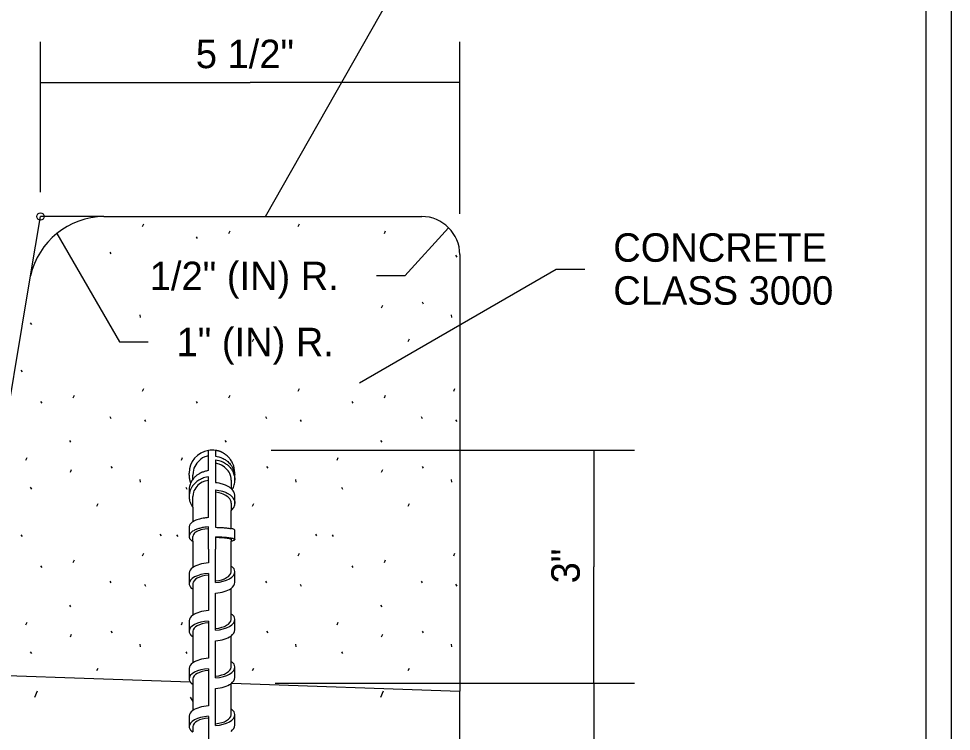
# Model space of a CAD drawing. Extents: x 99988 to 100172, y 99995 to 100047.
# Drawn here: x 100013.519 to 100015.812, y 100006.848 to 100008.601 of the extents above; entities that cross this region are included whole.
import ezdxf

# ---------------------------------------------------------------- set-up
doc = ezdxf.new("R2010")
doc.units = 0
for name, color, linetype in [('Level 1', 7, 'Continuous'), ('Level 10', 7, 'Continuous'), ('Level 15', 7, 'Continuous'), ('Level 2', 7, 'Continuous'), ('Level 20', 7, 'Continuous'), ('Level 3', 7, 'Continuous'), ('SH_GI_PlotLimits', 7, 'Continuous'), ('SH_GI_SheetBorder', 7, 'Continuous')]:
    doc.layers.add(name, color=color, linetype=linetype)

msp = doc.modelspace()

# ---------------------------------------------------------------- linework, layer by layer
at = {"layer": 'Level 1'}
for p, q in [((100013.7286, 100008.1139), (100014.51, 100008.1139)), ((100014.6037, 100008.0202), (100014.6037, 100006.9464)), ((100013.385, 100006.9889), (100013.5482, 100007.9682))]:
    msp.add_line(p, q, dxfattribs=at)
for centre, radius, start, end in [((100013.731, 100007.9264), 0.1875, 90.7439, 167.1228), ((100014.51, 100008.0202), 0.0937, 0, 90)]:
    msp.add_arc(centre, radius, start, end, dxfattribs=at)
at = {"layer": 'Level 10'}
for p, q in [((100013.9856, 100007.4889), (100013.9856, 100007.5387)), ((100014.0031, 100007.5387), (100014.0031, 100007.5247)), ((100014.0031, 100007.5157), (100014.0031, 100007.4599)), ((100013.9382, 100007.4781), (100013.9382, 100007.4828)), ((100013.9475, 100007.4678), (100013.9475, 100007.4781)), ((100013.9856, 100007.3733), (100013.9856, 100007.4736)), ((100014.0412, 100007.4656), (100014.0412, 100007.4451)), ((100014.0505, 100007.4656), (100014.0505, 100007.4742)), ((100013.9382, 100007.4413), (100013.9382, 100007.4251)), ((100014.0031, 100007.4418), (100014.0031, 100007.3495)), ((100013.9475, 100007.3987), (100013.9475, 100007.4251)), ((100014.0505, 100007.4086), (100014.0505, 100007.4265)), ((100013.9475, 100007.3987), (100013.9475, 100007.3631)), ((100014.0412, 100007.4086), (100014.0412, 100007.3902)), ((100014.0412, 100007.3464), (100014.0412, 100007.3902)), ((100013.9382, 100007.3503), (100013.9382, 100007.327)), ((100013.9856, 100007.2958), (100013.9856, 100007.3505)), ((100013.9475, 100007.3152), (100013.9475, 100007.327)), ((100014.0031, 100007.3264), (100014.0031, 100007.2958)), ((100014.0505, 100007.3196), (100014.0505, 100007.3426)), ((100013.9475, 100007.3152), (100013.9475, 100007.2958)), ((100014.0412, 100007.3196), (100014.0412, 100007.3158)), ((100014.0412, 100007.2958), (100014.0412, 100007.3158)), ((100013.9475, 100007.2958), (100013.9475, 100007.2508)), ((100014.0412, 100007.2538), (100014.0412, 100007.2958)), ((100014.0412, 100007.2402), (100014.0412, 100007.2538)), ((100013.9382, 100007.2368), (100013.9382, 100007.211)), ((100014.0505, 100007.2142), (100014.0505, 100007.2402)), ((100013.9475, 100007.211), (100013.9475, 100007.1979)), ((100013.9475, 100007.1979), (100013.9475, 100007.1336)), ((100014.0412, 100007.1366), (100014.0412, 100007.1992)), ((100013.9382, 100007.1196), (100013.9382, 100007.0939)), ((100014.0412, 100007.123), (100014.0412, 100007.1366)), ((100014.0412, 100007.1366), (100014.0412, 100007.1366)), ((100014.0505, 100007.097), (100014.0505, 100007.123)), ((100013.9475, 100007.0939), (100013.9475, 100007.0807)), ((100013.9475, 100007.0807), (100013.9475, 100007.0164)), ((100014.0412, 100007.0194), (100014.0412, 100007.0821)), ((100013.9382, 100007.0024), (100013.9382, 100006.9767)), ((100014.0412, 100007.0058), (100014.0412, 100007.0194)), ((100014.0505, 100006.9798), (100014.0505, 100007.0058)), ((100013.9475, 100006.9767), (100013.9475, 100006.9635)), ((100013.9475, 100006.9635), (100013.9475, 100006.8992)), ((100014.0412, 100006.9022), (100014.0412, 100006.9649)), ((100014.0412, 100006.8886), (100014.0412, 100006.9022)), ((100014.0505, 100006.8626), (100014.0505, 100006.8886)), ((100013.9382, 100006.8852), (100013.9382, 100006.8595)), ((100013.9475, 100006.8595), (100013.9475, 100006.8463))]:
    msp.add_line(p, q, dxfattribs=at)
for start, end in [(98.9444, 180.4882), (81.0556, 98.9444), (355.141, 17.7564)]:
    msp.add_arc((100013.9943, 100007.4833), 0.0561, start, end, dxfattribs=at)
for centre, major_axis, ratio, start_param, end_param in [((100013.9943, 100007.2368), (-0.0561, 0), 0.453331, 4.868499, 5.701022), ((100013.9943, 100007.211), (-0.0561, 0), 0.453331, 4.868499, 6.287318), ((100013.9943, 100007.2368), (-0.0561, 0), 0.453331, 5.701022, 6.28324), ((100013.9943, 100007.211), (-0.0469, 0), 0.453331, 4.899667, 6.283186), ((100013.9943, 100007.2402), (-0.0561, 0), 0.483341, 1.726906, 3.165641), ((100013.9943, 100007.2402), (0.0469, 0), 0.483341, 4.899667, 6.283186), ((100013.9943, 100007.2402), (-0.0561, 0), 0.483341, 3.165641, 3.398624), ((100013.9943, 100007.211), (-0.0561, 0), 0.453331, 0.005317, 0.291099), ((100013.9943, 100007.2142), (-0.0561, 0), 0.483341, 2.55865, 3.141593), ((100013.9943, 100007.2142), (-0.0561, 0), 0.483341, 1.726906, 2.55865), ((100013.9943, 100007.1196), (-0.0561, 0), 0.453331, 4.868499, 5.700703), ((100013.9943, 100007.0939), (-0.0561, 0), 0.453331, 4.868499, 6.289862), ((100013.9943, 100007.1196), (-0.0561, 0), 0.453331, 5.700723, 6.28324), ((100013.9943, 100007.123), (-0.0561, 0), 0.483341, 1.726906, 3.153527), ((100013.9943, 100007.123), (0.0469, 0), 0.483341, 4.899667, 6.283186), ((100013.9943, 100007.123), (-0.0561, 0), 0.483341, 3.153527, 3.398624), ((100013.9943, 100007.0939), (-0.0561, 0), 0.453331, 0.006676, 0.291099), ((100013.9943, 100007.0939), (-0.0469, 0), 0.453331, 4.899667, 6.283186), ((100013.9943, 100007.097), (-0.0561, 0), 0.483341, 2.558898, 3.141593), ((100013.9943, 100007.097), (-0.0561, 0), 0.483341, 1.726906, 2.558854), ((100013.9943, 100007.0024), (-0.0561, 0), 0.453331, 4.868499, 5.700722), ((100013.9943, 100006.9767), (-0.0561, 0), 0.453331, 4.868499, 6.28993), ((100013.9943, 100007.0024), (-0.0561, 0), 0.453331, 5.700722, 6.28324), ((100013.9943, 100007.0058), (-0.0561, 0), 0.483341, 1.726906, 3.170592), ((100013.9943, 100007.0058), (0.0469, 0), 0.483341, 4.899667, 6.283186), ((100013.9943, 100007.0058), (-0.0561, 0), 0.483341, 3.170592, 3.398624), ((100013.9943, 100006.9767), (-0.0469, 0), 0.453331, 4.899667, 6.283186), ((100013.9943, 100006.9798), (-0.0561, 0), 0.483341, 2.558843, 3.141593), ((100013.9943, 100006.9767), (-0.0561, 0), 0.453331, 0.006745, 0.291099), ((100013.9943, 100006.9798), (-0.0561, 0), 0.483341, 1.726906, 2.558843), ((100013.9943, 100006.8852), (-0.0561, 0), 0.453331, 4.868499, 5.701512), ((100013.9943, 100006.8852), (-0.0561, 0), 0.453331, 5.701512, 6.28324), ((100013.9943, 100006.8886), (-0.0561, 0), 0.483341, 1.726906, 3.160103), ((100013.9943, 100006.8886), (0.0469, 0), 0.483341, 4.899667, 6.283186), ((100013.9943, 100006.8886), (-0.0561, 0), 0.483341, 3.161599, 3.398624), ((100013.9943, 100006.8595), (-0.0561, 0), 0.453331, 4.868499, 6.300734), ((100013.9943, 100006.8595), (-0.0469, 0), 0.453331, 4.899667, 6.283186), ((100013.9943, 100006.8595), (-0.0561, 0), 0.453331, 0.017549, 0.291099), ((100013.9943, 100006.8626), (-0.0561, 0), 0.483341, 2.559264, 3.141593)]:
    msp.add_ellipse(centre, major_axis=major_axis, ratio=ratio, start_param=start_param, end_param=end_param, dxfattribs=at)
for points, degree in [([(100014.0236, 100007.5312), (100014.0173, 100007.535), (100014.0103, 100007.5376), (100014.0031, 100007.5387)], 2), ([(100014.0478, 100007.5004), (100014.0459, 100007.5064), (100014.0429, 100007.5122), (100014.0368, 100007.5202), (100014.0344, 100007.5227), (100014.0293, 100007.5273), (100014.0266, 100007.5294), (100014.0236, 100007.5312)], 3), ([(100013.9856, 100007.5254), (100013.9719, 100007.5217), (100013.9631, 100007.5155), (100013.9508, 100007.4989), (100013.9475, 100007.4885), (100013.9475, 100007.4781)], 3), ([(100014.0031, 100007.5247), (100014.0096, 100007.5237), (100014.016, 100007.5217), (100014.0276, 100007.5158), (100014.0328, 100007.5119), (100014.0414, 100007.5027), (100014.0448, 100007.4974), (100014.0488, 100007.4875), (100014.0499, 100007.4829), (100014.0503, 100007.4784)], 3), ([(100014.0031, 100007.5157), (100014.0164, 100007.5126), (100014.0222, 100007.51), (100014.0324, 100007.5034), (100014.0369, 100007.4992), (100014.044, 100007.4899), (100014.0468, 100007.4846), (100014.0498, 100007.4747), (100014.0505, 100007.4701), (100014.0505, 100007.4655)], 3), ([(100014.0412, 100007.4656), (100014.0412, 100007.4656), (100014.0412, 100007.4656), (100014.0412, 100007.4749), (100014.0377, 100007.4842), (100014.0254, 100007.4985), (100014.0169, 100007.5038), (100014.0031, 100007.5074)], 3), ([(100013.9856, 100007.4889), (100013.981, 100007.4883), (100013.9765, 100007.4871), (100013.9679, 100007.484), (100013.9639, 100007.482), (100013.9565, 100007.4771), (100013.9531, 100007.4743), (100013.9474, 100007.468), (100013.9449, 100007.4646), (100013.9426, 100007.46), (100013.9421, 100007.459), (100013.9416, 100007.458)], 3), ([(100013.9382, 100007.4781), (100013.9382, 100007.4738), (100013.9386, 100007.4699), (100013.9394, 100007.4661)], 2), ([(100013.9856, 100007.4736), (100013.978, 100007.4726), (100013.9706, 100007.4701), (100013.9609, 100007.4648), (100013.9579, 100007.4626), (100013.9524, 100007.458), (100013.95, 100007.4555), (100013.9436, 100007.4472), (100013.9407, 100007.441), (100013.9386, 100007.4316), (100013.9382, 100007.4286), (100013.9382, 100007.4256)], 3), ([(100013.9394, 100007.4661), (100013.94, 100007.4634), (100013.9407, 100007.4606), (100013.9417, 100007.458)], 2), ([(100013.9856, 100007.4651), (100013.9712, 100007.4619), (100013.9629, 100007.4568), (100013.9508, 100007.4428), (100013.9475, 100007.4341), (100013.9475, 100007.4251)], 3), ([(100014.0031, 100007.4599), (100014.0096, 100007.4593), (100014.016, 100007.4579), (100014.0276, 100007.454), (100014.0328, 100007.4514), (100014.0399, 100007.4464), (100014.0422, 100007.4443), (100014.0442, 100007.442)], 3), ([(100014.0441, 100007.4421), (100014.0448, 100007.4433), (100014.0454, 100007.4445), (100014.0484, 100007.4509), (100014.0499, 100007.4565), (100014.0504, 100007.4633), (100014.0505, 100007.4644), (100014.0505, 100007.4655)], 3), ([(100014.0505, 100007.4742), (100014.0505, 100007.4756), (100014.0504, 100007.477), (100014.0503, 100007.4784)], 2), ([(100013.9416, 100007.458), (100013.9405, 100007.4552), (100013.9396, 100007.4524), (100013.9385, 100007.4467), (100013.9382, 100007.4439), (100013.9382, 100007.441)], 3), ([(100014.0031, 100007.4418), (100014.0164, 100007.4398), (100014.0222, 100007.438), (100014.0324, 100007.4336), (100014.0369, 100007.4309), (100014.044, 100007.4247), (100014.0468, 100007.4212), (100014.0498, 100007.4146), (100014.0505, 100007.4115), (100014.0505, 100007.4084)], 3), ([(100014.0412, 100007.4086), (100014.0412, 100007.4086), (100014.0412, 100007.4086), (100014.0412, 100007.4148), (100014.0377, 100007.421), (100014.0254, 100007.4304), (100014.0169, 100007.4339), (100014.0031, 100007.4363)], 3), ([(100014.0505, 100007.4265), (100014.0505, 100007.4304), (100014.0493, 100007.4344), (100014.0462, 100007.4394), (100014.0453, 100007.4407), (100014.0442, 100007.442)], 3), ([(100013.9382, 100007.4256), (100013.9382, 100007.422), (100013.9386, 100007.4184), (100013.9394, 100007.4149)], 2), ([(100013.9394, 100007.4149), (100013.9406, 100007.4098), (100013.9428, 100007.405), (100013.9464, 100007.4001), (100013.9469, 100007.3995), (100013.9475, 100007.3988)], 3), ([(100014.0412, 100007.3902), (100014.0431, 100007.3918), (100014.0446, 100007.3936), (100014.0484, 100007.3989), (100014.0499, 100007.4026), (100014.0504, 100007.4071), (100014.0505, 100007.4077), (100014.0505, 100007.4084)], 3), ([(100013.9856, 100007.3733), (100013.981, 100007.373), (100013.9765, 100007.3725), (100013.9679, 100007.371), (100013.9639, 100007.37), (100013.9565, 100007.3676), (100013.9531, 100007.3663), (100013.9493, 100007.3642), (100013.9483, 100007.3637), (100013.9474, 100007.3631)], 3), ([(100013.9474, 100007.3631), (100013.9458, 100007.3621), (100013.9443, 100007.3609), (100013.9412, 100007.358), (100013.9398, 100007.3562), (100013.9385, 100007.3529), (100013.9382, 100007.3515), (100013.9382, 100007.3501)], 3), ([(100013.9856, 100007.3505), (100013.978, 100007.35), (100013.9706, 100007.3489), (100013.9609, 100007.3462), (100013.9579, 100007.3452), (100013.9524, 100007.343), (100013.95, 100007.3417), (100013.9436, 100007.3377), (100013.9407, 100007.3347), (100013.9385, 100007.3301), (100013.9382, 100007.3285), (100013.9382, 100007.327)], 3), ([(100013.9856, 100007.3462), (100013.9722, 100007.3451), (100013.9632, 100007.3425), (100013.9508, 100007.3356), (100013.9475, 100007.3313), (100013.9475, 100007.327)], 3), ([(100014.0031, 100007.3495), (100014.0096, 100007.3493), (100014.016, 100007.3491), (100014.0276, 100007.3483), (100014.0328, 100007.3477), (100014.0386, 100007.3469), (100014.0399, 100007.3467), (100014.0412, 100007.3465)], 3), ([(100014.0505, 100007.3426), (100014.0505, 100007.3434), (100014.0493, 100007.3443), (100014.0456, 100007.3455), (100014.0436, 100007.346), (100014.0412, 100007.3465)], 3), ([(100013.9382, 100007.327), (100013.9382, 100007.3254), (100013.9386, 100007.3237), (100013.9394, 100007.3221)], 2), ([(100013.9394, 100007.3221), (100013.9406, 100007.3196), (100013.9428, 100007.3175), (100013.9464, 100007.3157), (100013.9469, 100007.3154), (100013.9475, 100007.3152)], 3), ([(100014.0031, 100007.3264), (100014.0056, 100007.3263), (100014.008, 100007.3262), (100014.0104, 100007.3262)], 2), ([(100014.0031, 100007.3251), (100014.0171, 100007.3247), (100014.0255, 100007.324), (100014.0377, 100007.3221), (100014.0412, 100007.3208), (100014.0412, 100007.3196), (100014.0412, 100007.3196), (100014.0412, 100007.3196)], 3), ([(100014.0104, 100007.3262), (100014.0164, 100007.3259), (100014.0222, 100007.3256), (100014.0324, 100007.3247), (100014.0369, 100007.3241), (100014.044, 100007.3229), (100014.0468, 100007.3221), (100014.0498, 100007.3208), (100014.0505, 100007.3202), (100014.0505, 100007.3196)], 3), ([(100014.0412, 100007.3158), (100014.0431, 100007.3161), (100014.0446, 100007.3165), (100014.0484, 100007.3176), (100014.0499, 100007.3183), (100014.0504, 100007.3193), (100014.0505, 100007.3194), (100014.0505, 100007.3196)], 3), ([(100013.9856, 100007.2958), (100013.9856, 100007.2926), (100013.9856, 100007.2895), (100013.9856, 100007.2864), (100013.9856, 100007.2782), (100013.9856, 100007.2701), (100013.9856, 100007.2619)], 3), ([(100014.0031, 100007.2134), (100014.0031, 100007.2163), (100014.0031, 100007.2192), (100014.0031, 100007.2221), (100014.0031, 100007.2346), (100014.0031, 100007.2471), (100014.0031, 100007.2596), (100014.0031, 100007.2717), (100014.0031, 100007.2837), (100014.0031, 100007.2958)], 3), ([(100014.0486, 100007.2471), (100014.0472, 100007.2496), (100014.0451, 100007.2518), (100014.0418, 100007.2535), (100014.0415, 100007.2537), (100014.0412, 100007.2538)], 3), ([(100013.9856, 100007.2362), (100013.9856, 100007.2333), (100013.9856, 100007.2304), (100013.9856, 100007.2275), (100013.9856, 100007.215), (100013.9856, 100007.2025), (100013.9856, 100007.19), (100013.9856, 100007.1749), (100013.9856, 100007.1598), (100013.9856, 100007.1447)], 3), ([(100013.9406, 100007.2037), (100013.9421, 100007.2014), (100013.9444, 100007.1994), (100013.9475, 100007.1979)], 2), ([(100014.0031, 100007.0962), (100014.0031, 100007.0991), (100014.0031, 100007.102), (100014.0031, 100007.1049), (100014.0031, 100007.1174), (100014.0031, 100007.1299), (100014.0031, 100007.1424), (100014.0031, 100007.1574), (100014.0031, 100007.1724), (100014.0031, 100007.1874)], 3), ([(100013.9856, 100007.119), (100013.9856, 100007.1161), (100013.9856, 100007.1132), (100013.9856, 100007.1103), (100013.9856, 100007.0978), (100013.9856, 100007.0853), (100013.9856, 100007.0728), (100013.9856, 100007.0577), (100013.9856, 100007.0426), (100013.9856, 100007.0275)], 3), ([(100014.0486, 100007.1299), (100014.0472, 100007.1324), (100014.0451, 100007.1346), (100014.0418, 100007.1363), (100014.0415, 100007.1365), (100014.0412, 100007.1366)], 3), ([(100013.9406, 100007.0866), (100013.9421, 100007.0843), (100013.9444, 100007.0823), (100013.9475, 100007.0807)], 2), ([(100014.0031, 100006.979), (100014.0031, 100006.9819), (100014.0031, 100006.9848), (100014.0031, 100006.9877), (100014.0031, 100007.0002), (100014.0031, 100007.0127), (100014.0031, 100007.0252), (100014.0031, 100007.0402), (100014.0031, 100007.0552), (100014.0031, 100007.0702)], 3), ([(100013.9856, 100007.0018), (100013.9856, 100006.9989), (100013.9856, 100006.996), (100013.9856, 100006.9931), (100013.9856, 100006.9806), (100013.9856, 100006.9681), (100013.9856, 100006.9556), (100013.9856, 100006.9405), (100013.9856, 100006.9254), (100013.9856, 100006.9104)], 3), ([(100014.0486, 100007.0127), (100014.0472, 100007.0153), (100014.0451, 100007.0174), (100014.0418, 100007.0192), (100014.0415, 100007.0193), (100014.0412, 100007.0194)], 3), ([(100013.9406, 100006.9694), (100013.9421, 100006.9671), (100013.9444, 100006.9651), (100013.9475, 100006.9635)], 2), ([(100014.0031, 100006.8618), (100014.0031, 100006.8647), (100014.0031, 100006.8676), (100014.0031, 100006.8705), (100014.0031, 100006.883), (100014.0031, 100006.8955), (100014.0031, 100006.908), (100014.0031, 100006.923), (100014.0031, 100006.938), (100014.0031, 100006.953)], 3), ([(100014.0486, 100006.8955), (100014.0472, 100006.8981), (100014.0451, 100006.9002), (100014.0418, 100006.902), (100014.0415, 100006.9021), (100014.0412, 100006.9022)], 3), ([(100013.9856, 100006.8846), (100013.9856, 100006.8817), (100013.9856, 100006.8788), (100013.9856, 100006.876), (100013.9856, 100006.8635), (100013.9856, 100006.851), (100013.9856, 100006.8385), (100013.9856, 100006.8234), (100013.9856, 100006.8083), (100013.9856, 100006.7932)], 3), ([(100013.9406, 100006.8522), (100013.9421, 100006.8499), (100013.9444, 100006.8479), (100013.9475, 100006.8463)], 2)]:
    msp.add_open_spline(points, degree=degree, dxfattribs=at)
at = {"layer": 'Level 15'}
for p, q in [((100013.5725, 100008.1739), (100013.5725, 100008.5439)), ((100014.6037, 100008.1202), (100014.6037, 100008.5439)), ((100013.5725, 100008.4439), (100014.0881, 100008.4439)), ((100014.6037, 100008.4439), (100014.0881, 100008.4439)), ((100013.5482, 100007.9682), (100013.5725, 100008.1139)), ((100013.7286, 100008.1139), (100013.5725, 100008.1139)), ((100014.1399, 100007.5394), (100015.0337, 100007.5394)), ((100014.9337, 100007.5394), (100014.9337, 100007.2527)), ((100014.9337, 100006.966), (100014.9337, 100007.2527)), ((100014.1495, 100006.966), (100015.0337, 100006.966)), ((100014.9337, 100006.966), (100014.9337, 100006.2402))]:
    msp.add_line(p, q, dxfattribs=at)
for points in [[(100014.1259, 100008.1139), (100014.4938, 100008.7627), (100014.5638, 100008.7627)], [(100014.5763, 100008.0865), (100014.4687, 100007.9679), (100014.3987, 100007.9679)], [(100013.6132, 100008.0723), (100013.7673, 100007.8054), (100013.8373, 100007.8054)], [(100014.3573, 100007.7053), (100014.8411, 100007.9849), (100014.9111, 100007.9849)]]:
    msp.add_lwpolyline(points, dxfattribs=at)
msp.add_circle((100013.5725, 100008.1139), 0.0089, dxfattribs=at)
at = {"layer": 'Level 2'}
for p, q in [((100010.5785, 100007.0869), (100013.9406, 100006.9695)), ((100014.0426, 100006.966), (100014.6037, 100006.9464)), ((100014.6037, 100005.2589), (100014.6037, 100006.9464))]:
    msp.add_line(p, q, dxfattribs=at)
at = {"layer": 'Level 3'}
for p, q in [((100013.8237, 100008.0891), (100013.8266, 100008.0956)), ((100014.0359, 100008.0725), (100014.0388, 100008.079)), ((100014.2064, 100008.0891), (100014.2092, 100008.0956)), ((100014.4185, 100008.0725), (100014.4214, 100008.079)), ((100013.9554, 100008.0641), (100013.9583, 100008.0598)), ((100013.7432, 100008.0265), (100013.746, 100008.0222)), ((100014.5934, 100008.0187), (100014.5963, 100008.0144)), ((100014.4113, 100007.8898), (100014.4142, 100007.8963)), ((100014.5111, 100007.9038), (100014.514, 100007.8995)), ((100013.5472, 100007.8527), (100013.5501, 100007.8484)), ((100013.8171, 100007.8718), (100013.8178, 100007.8653)), ((100014.5824, 100007.8718), (100014.5831, 100007.8653)), ((100014.0942, 100007.8064), (100014.097, 100007.8129)), ((100014.4768, 100007.8064), (100014.4797, 100007.8129)), ((100013.5245, 100007.736), (100013.5274, 100007.7317)), ((100013.8237, 100007.6844), (100013.8266, 100007.6908)), ((100014.2064, 100007.6844), (100014.2092, 100007.6908)), ((100014.589, 100007.6844), (100014.5919, 100007.6908)), ((100013.6532, 100007.6678), (100013.6561, 100007.6743)), ((100014.0359, 100007.6678), (100014.0388, 100007.6743)), ((100014.4185, 100007.6678), (100014.4214, 100007.6743)), ((100013.5727, 100007.6594), (100013.5756, 100007.6551)), ((100013.9554, 100007.6594), (100013.9583, 100007.6551)), ((100014.338, 100007.6594), (100014.3409, 100007.6551)), ((100013.7432, 100007.6218), (100013.746, 100007.6175)), ((100014.1258, 100007.6218), (100014.1287, 100007.6175)), ((100014.5084, 100007.6218), (100014.5113, 100007.6175)), ((100013.8282, 100007.614), (100013.831, 100007.6097)), ((100014.2108, 100007.614), (100014.2137, 100007.6097)), ((100014.5934, 100007.614), (100014.5963, 100007.6097)), ((100013.6437, 100007.5629), (100013.6466, 100007.5586)), ((100014.0263, 100007.5629), (100014.0292, 100007.5586)), ((100014.409, 100007.5629), (100014.4119, 100007.5586)), ((100013.5367, 100007.5146), (100013.5396, 100007.5211)), ((100013.9194, 100007.5146), (100013.9222, 100007.5211)), ((100014.302, 100007.5146), (100014.3049, 100007.5211)), ((100013.6461, 100007.4851), (100013.6489, 100007.4916)), ((100013.7459, 100007.4991), (100013.7487, 100007.4947)), ((100014.1285, 100007.4991), (100014.1314, 100007.4947)), ((100014.4113, 100007.4851), (100014.4142, 100007.4916)), ((100014.5111, 100007.4991), (100014.514, 100007.4947)), ((100013.8171, 100007.4671), (100013.8178, 100007.4606)), ((100014.1997, 100007.4671), (100014.2004, 100007.4606)), ((100014.5824, 100007.4671), (100014.5831, 100007.4606)), ((100013.5472, 100007.448), (100013.5501, 100007.4437)), ((100013.9298, 100007.448), (100013.9327, 100007.4437)), ((100014.3125, 100007.448), (100014.3154, 100007.4437)), ((100013.7115, 100007.4017), (100013.7144, 100007.4082)), ((100014.0942, 100007.4017), (100014.097, 100007.4082)), ((100014.4768, 100007.4017), (100014.4797, 100007.4082)), ((100013.5245, 100007.3313), (100013.5274, 100007.327)), ((100013.8662, 100007.333), (100013.869, 100007.3287)), ((100013.9071, 100007.3313), (100013.91, 100007.327)), ((100014.2488, 100007.333), (100014.2517, 100007.3287)), ((100014.2898, 100007.3313), (100014.2926, 100007.327)), ((100013.8237, 100007.2797), (100013.8266, 100007.2861)), ((100014.2064, 100007.2797), (100014.2092, 100007.2861)), ((100014.589, 100007.2797), (100014.5919, 100007.2861)), ((100013.5727, 100007.2547), (100013.5756, 100007.2504)), ((100013.6532, 100007.2631), (100013.6561, 100007.2696)), ((100014.338, 100007.2547), (100014.3409, 100007.2504)), ((100014.4185, 100007.2631), (100014.4214, 100007.2696)), ((100013.7432, 100007.2171), (100013.746, 100007.2128)), ((100013.8282, 100007.2093), (100013.831, 100007.205)), ((100014.1258, 100007.2171), (100014.1287, 100007.2128)), ((100014.2108, 100007.2093), (100014.2137, 100007.205)), ((100014.5084, 100007.2171), (100014.5113, 100007.2128)), ((100014.5934, 100007.2093), (100014.5963, 100007.205)), ((100013.6437, 100007.1582), (100013.6466, 100007.1539)), ((100014.409, 100007.1582), (100014.4119, 100007.1539)), ((100013.5367, 100007.1099), (100013.5396, 100007.1164)), ((100013.9194, 100007.1099), (100013.9222, 100007.1164)), ((100014.302, 100007.1099), (100014.3049, 100007.1164)), ((100013.7459, 100007.0944), (100013.7487, 100007.09)), ((100014.1285, 100007.0944), (100014.1314, 100007.09)), ((100014.5111, 100007.0944), (100014.514, 100007.09)), ((100013.6461, 100007.0804), (100013.6489, 100007.0869)), ((100014.4113, 100007.0804), (100014.4142, 100007.0869)), ((100013.8171, 100007.0623), (100013.8178, 100007.0559)), ((100014.1997, 100007.0623), (100014.2004, 100007.0559)), ((100014.5824, 100007.0623), (100014.5831, 100007.0559)), ((100013.5472, 100007.0433), (100013.5501, 100007.039)), ((100013.9298, 100007.0433), (100013.9327, 100007.039)), ((100014.3125, 100007.0433), (100014.3154, 100007.039)), ((100013.7115, 100006.997), (100013.7144, 100007.0034)), ((100014.0942, 100006.997), (100014.097, 100007.0034)), ((100014.4768, 100006.997), (100014.4797, 100007.0034)), ((100013.5584, 100006.9315), (100013.5655, 100006.9475)), ((100013.9403, 100006.9315), (100013.9474, 100006.9208)), ((100014.4092, 100006.9315), (100014.4163, 100006.9475)), ((100013.9474, 100006.9274), (100013.9475, 100006.9273))]:
    msp.add_line(p, q, dxfattribs=at)
at = {"layer": 'SH_GI_PlotLimits'}
msp.add_lwpolyline([(99999.3125, 99999.9375), (100015.8125, 99999.9375), (100015.8125, 100010.4375), (99999.3125, 100010.4375)], close=True, dxfattribs=at)
at = {"layer": 'SH_GI_SheetBorder'}
msp.add_line((100015.75, 100010.375), (100015.75, 100000), dxfattribs=at)

# ---------------------------------------------------------------- texts
at = {"layer": 'Level 20'}
for s, p in [('5 1/2"', (100013.9546, 100008.4789)), ('1/2" (IN) R.', (100013.8414, 100007.9329))]:
    msp.add_text(s, height=0.07, dxfattribs=at).set_placement(p)
for s, rotation, p in [('CONCRETE', 360, (100014.9811, 100008.0027)), ('CLASS 3000', 360, (100014.9811, 100007.8971)), ('1" (IN) R.', 360, (100013.9073, 100007.7704)), ('3"', 90, (100014.8987, 100007.2117))]:
    msp.add_text(s, height=0.07, rotation=rotation, dxfattribs=at).set_placement(p)

doc.saveas('drawing.dxf')
